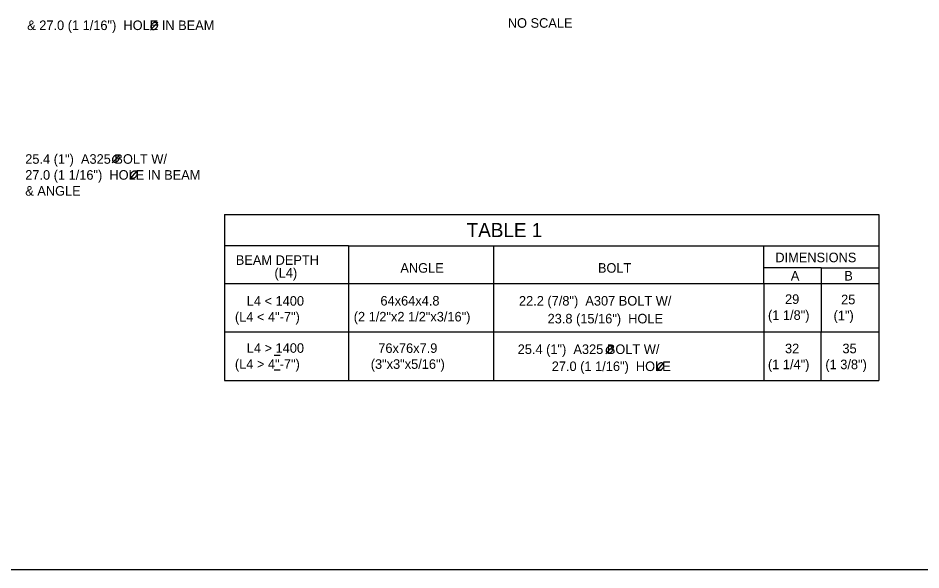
# Model space of a CAD drawing. Extents: x 638263 to 640360, y 293683 to 298655.
# Drawn here: x 639617.3 to 639900.5, y 297262.5 to 297435.6 of the extents above; entities that cross this region are included whole.
import ezdxf

# ---------------------------------------------------------------- set-up
doc = ezdxf.new("R2010")
doc.units = 0
for name, color, linetype in [('2', 7, 'Continuous'), ('3', 7, 'Continuous'), ('4', 7, 'Continuous'), ('5', 7, 'Continuous')]:
    doc.layers.add(name, color=color, linetype=linetype)

msp = doc.modelspace()

# ---------------------------------------------------------------- linework, layer by layer
at = {"layer": '2'}
msp.add_line((640102.46, 297262.46), (639316.46, 297262.46), dxfattribs=at)
at = {"layer": '3'}
for p, q in [((639697.68, 297329.84), (639699.57, 297329.84)), ((639697.68, 297325.23), (639699.57, 297325.23))]:
    msp.add_line(p, q, dxfattribs=at)
at = {"layer": '4'}
for p, q in [((639658.89, 297431.76), (639661.13, 297434.22)), ((639646.85, 297390.14), (639649.09, 297392.59)), ((639652.46, 297385.16), (639654.7, 297387.61)), ((639801.72, 297330.27), (639803.96, 297332.72)), ((639817.67, 297324.95), (639819.91, 297327.41))]:
    msp.add_line(p, q, dxfattribs=at)
for points in [[(639660.9, 297433.97), (639660.72, 297434.11), (639660.55, 297434.16), (639660.33, 297434.18), (639660.2, 297434.18), (639659.99, 297434.13), (639659.79, 297434.04), (639659.65, 297433.96), (639659.39, 297433.75), (639659.18, 297433.48), (639659.06, 297433.23), (639658.98, 297432.99), (639658.96, 297432.78), (639658.98, 297432.59), (639659.08, 297432.33), (639659.17, 297432.19), (639659.36, 297432.05), (639659.65, 297431.98), (639659.98, 297431.99), (639660.4, 297432.18), (639660.7, 297432.44), (639660.93, 297432.76), (639661.08, 297433.09), (639661.13, 297433.46), (639661.07, 297433.69), (639660.91, 297433.97)], [(639648.86, 297392.35), (639648.68, 297392.49), (639648.51, 297392.54), (639648.29, 297392.56), (639648.16, 297392.56), (639647.95, 297392.51), (639647.75, 297392.42), (639647.61, 297392.34), (639647.35, 297392.13), (639647.14, 297391.86), (639647.02, 297391.61), (639646.94, 297391.37), (639646.92, 297391.16), (639646.94, 297390.97), (639647.04, 297390.71), (639647.13, 297390.57), (639647.32, 297390.43), (639647.61, 297390.36), (639647.94, 297390.37), (639648.36, 297390.56), (639648.66, 297390.82), (639648.89, 297391.14), (639649.04, 297391.47), (639649.09, 297391.84), (639649.03, 297392.07), (639648.87, 297392.35)], [(639654.46, 297387.37), (639654.29, 297387.5), (639654.11, 297387.55), (639653.9, 297387.57), (639653.77, 297387.57), (639653.55, 297387.52), (639653.35, 297387.43), (639653.22, 297387.35), (639652.95, 297387.14), (639652.75, 297386.87), (639652.62, 297386.62), (639652.55, 297386.39), (639652.53, 297386.17), (639652.55, 297385.99), (639652.64, 297385.72), (639652.74, 297385.59), (639652.93, 297385.44), (639653.21, 297385.37), (639653.55, 297385.38), (639653.96, 297385.57), (639654.27, 297385.83), (639654.5, 297386.15), (639654.65, 297386.48), (639654.7, 297386.85), (639654.63, 297387.09), (639654.48, 297387.37)], [(639803.73, 297332.48), (639803.56, 297332.62), (639803.38, 297332.67), (639803.16, 297332.68), (639803.04, 297332.68), (639802.82, 297332.64), (639802.62, 297332.54), (639802.49, 297332.47), (639802.22, 297332.26), (639802.01, 297331.99), (639801.89, 297331.73), (639801.82, 297331.5), (639801.79, 297331.29), (639801.82, 297331.1), (639801.91, 297330.84), (639802, 297330.7), (639802.19, 297330.56), (639802.48, 297330.49), (639802.81, 297330.5), (639803.23, 297330.69), (639803.54, 297330.95), (639803.77, 297331.27), (639803.92, 297331.6), (639803.97, 297331.97), (639803.9, 297332.2), (639803.74, 297332.48)], [(639819.68, 297327.16), (639819.5, 297327.3), (639819.33, 297327.35), (639819.11, 297327.37), (639818.98, 297327.37), (639818.77, 297327.32), (639818.57, 297327.23), (639818.43, 297327.15), (639818.17, 297326.94), (639817.96, 297326.67), (639817.84, 297326.42), (639817.76, 297326.18), (639817.74, 297325.97), (639817.76, 297325.78), (639817.85, 297325.52), (639817.95, 297325.38), (639818.14, 297325.24), (639818.43, 297325.17), (639818.76, 297325.18), (639819.18, 297325.37), (639819.48, 297325.63), (639819.71, 297325.95), (639819.86, 297326.28), (639819.91, 297326.65), (639819.85, 297326.88), (639819.69, 297327.16)]]:
    msp.add_spline(points, degree=3, dxfattribs=at)
at = {"layer": '5'}
for p, q in [((639682.04, 297373.99), (639682.04, 297321.9)), ((639682.04, 297373.99), (639887.32, 297373.99)), ((639887.32, 297373.99), (639887.32, 297357.18)), ((639721, 297364.15), (639682.04, 297364.15)), ((639721, 297364.15), (639721, 297321.9)), ((639721, 297364.15), (639766.4, 297364.15)), ((639766.4, 297364.15), (639766.4, 297321.9)), ((639766.4, 297364.15), (639887.32, 297364.15)), ((639851.2, 297352.26), (639851.2, 297364.15)), ((639869.26, 297357.18), (639851.2, 297357.18)), ((639869.26, 297357.18), (639887.32, 297357.18)), ((639869.26, 297357.18), (639869.26, 297352.26)), ((639887.32, 297357.18), (639887.32, 297321.9)), ((639682.04, 297352.26), (639721, 297352.26)), ((639721, 297352.26), (639766.4, 297352.26)), ((639766.4, 297352.26), (639851.2, 297352.26)), ((639851.2, 297352.26), (639851.2, 297321.9)), ((639851.2, 297352.26), (639869.26, 297352.26)), ((639869.26, 297352.26), (639887.32, 297352.26)), ((639869.26, 297352.26), (639869.26, 297337.11)), ((639682.04, 297337.11), (639721, 297337.11)), ((639721, 297337.11), (639766.4, 297337.11)), ((639766.4, 297337.11), (639851.2, 297337.11)), ((639851.2, 297337.11), (639869.26, 297337.11)), ((639869.26, 297337.11), (639887.32, 297337.11)), ((639869.26, 297321.9), (639869.26, 297337.11)), ((639682.04, 297321.9), (639721, 297321.9)), ((639721, 297321.9), (639766.4, 297321.9)), ((639766.4, 297321.9), (639851.2, 297321.9)), ((639851.2, 297321.9), (639887.32, 297321.9))]:
    msp.add_line(p, q, dxfattribs=at)

# ---------------------------------------------------------------- texts
at = {"layer": '3'}
for s, height, p in [('& 27.0 (1 1/16")  HOLE IN BEAM', 3, (639620.18, 297431.79)), ('NO SCALE', 3, (639770.94, 297432.51)), ('25.4 (1")  A325 BOLT W/', 3, (639619.57, 297389.85)), ('27.0 (1 1/16")  HOLE IN BEAM', 3, (639619.57, 297384.85)), ('& ANGLE', 3, (639619.57, 297379.85)), ('TABLE 1', 4.429, (639758.04, 297366.86)), ('BEAM DEPTH', 3, (639685.62, 297358.14)), ('DIMENSIONS', 3, (639854.86, 297358.97)), ('ANGLE', 3, (639737.24, 297355.68)), ('BOLT', 3, (639799.21, 297355.68)), ('(L4)', 3, (639697.74, 297354.14)), ('A', 3, (639859.71, 297353.22)), ('B', 3, (639876.49, 297353.22)), ('29', 3, (639857.9, 297345.89)), ('L4 < 1400', 3, (639689.06, 297345.34)), ('64x64x4.8', 3, (639730.99, 297345.39)), ('22.2 (7/8")  A307 BOLT W/', 3, (639774.44, 297345.37)), ('25', 3, (639875.48, 297345.78)), ('(L4 < 4"-7")', 3, (639685.34, 297340.34)), ('(2 1/2"x2 1/2"x3/16")', 3, (639722.61, 297340.39)), ('(1 1/8")', 3, (639852.55, 297340.89)), ('(1")', 3, (639873.12, 297340.78)), ('23.8 (15/16")  HOLE', 3, (639783.42, 297339.78)), ('L4 > 1400', 3, (639689.06, 297330.56)), ('76x76x7.9', 3, (639730.32, 297330.53)), ('25.4 (1")  A325 BOLT W/', 3, (639774.04, 297330.19)), ('32', 3, (639857.89, 297330.42)), ('35', 3, (639875.9, 297330.42)), ('(L4 > 4"-7")', 3, (639685.34, 297325.56)), ('(3"x3"x5/16")', 3, (639727.95, 297325.53)), ('27.0 (1 1/16")  HOLE', 3, (639784.72, 297324.84)), ('(1 1/4")', 3, (639852.53, 297325.42)), ('(1 3/8")', 3, (639870.54, 297325.42))]:
    msp.add_text(s, height=height, dxfattribs=at).set_placement(p)

doc.saveas('drawing.dxf')
